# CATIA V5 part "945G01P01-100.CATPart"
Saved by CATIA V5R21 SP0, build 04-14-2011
Part number: 945G01P01-100
Bounding box of the stored display mesh (mm): x -11.215 to 11.225, y -4.875 to 4.875, z -50.1 to 50.1
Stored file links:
  C:\Users\ALI OZGUN\Desktop\alhan\945G01P01-100.CATPart
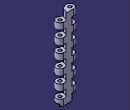
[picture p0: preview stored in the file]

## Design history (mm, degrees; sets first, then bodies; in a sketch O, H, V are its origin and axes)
Body1 (main body)
  Sketch1 on xy-plane, origin (0, 0, 0), H (1, 0, 0), V (0, 1, 0)
    construction line L1 (-6.35, 0) -> (6.35, 0)
    point P1 (-6.35, 0)
    point P2 (6.35, 0)
    line L2 (-6.35, 4.875) -> (6.35, 4.875)
    line L3 (6.35, -4.875) -> (-6.35, -4.875)
    arc A1 centre (6.35, 0) radius 4.875 from (6.35, 4.875) to (6.35, -4.875) cw
    arc A2 centre (-6.35, 0) radius 4.875 from (-6.35, -4.875) to (-6.35, 4.875) cw
    distance L1 L2 = 4.875
    length L1 = 12.7
    distance P2 V = 6.35
    coincidence: P1 H
    horizontal: L1 H
    tangency: A1 L2, A2 L2, A1 L3, A2 L3
  Pad1: profile Sketch1, direction (0, 0, 1), length 50.1, mirrored extent
  Body2
    Sketch2 on zx-plane, origin (0, 0, 0), H (-1, 0, 0), V (0, 0, 1)
      line L1 (-17.4249, -33.3) -> (-3.75, -33.3)
      line L2 (-3.75, -33.3) -> (-3.75, -42.1)
      line L3 (-3.75, -42.1) -> (-17.4249, -42.1)
      line L4 (-17.4249, -42.1) -> (-17.4249, -33.3)
      line L5 (3.75, -41.7) -> (15.9148, -41.7)
      line L6 (15.9148, -41.7) -> (15.9148, -50.5)
      line L7 (15.9148, -50.5) -> (3.75, -50.5)
      line L8 (3.75, -50.5) -> (3.75, -41.7)
      reference projected line E1 (-6.35, -50.1) -> (6.35, -50.1) from edge [start face of Pad1 | face of Pad1 from Sketch1.L2]
      reference projected line E2 (-6.35, -50.1) -> (6.35, -50.1) from edge [start face of Pad1 | face of Pad1 from Sketch1.L2]
      distance L3 E1 = 8
      length L4 = 8.8
      distance L2 L8 = 7.5
      distance L8 V = 3.75
      distance L5 L7 = 8.8
      distance L5 E2 = 8.4
      horizontal: L1 H, L3 H, L5 H, L7 H
      vertical: L2 V, L4 V, L6 V, L8 V
    Pad2: profile Sketch2, direction (0, 1, 0), length 20, mirrored extent
    RectPattern1: of the body so far, direction 1 instances 6, spacing 16.8, along axis of face of Pad1 from Sketch1.A2
  Remove1: tool Body2
  Sketch3 on xy-plane, origin (0, 0, 0), H (1, 0, 0), V (0, 1, 0)
    line L1 (-2.8809, -3.425) -> (2.8809, -3.425)
    reference projected line E1 (6.35, 4.875) -> (-6.35, 4.875) from edge [face of Pad1 from Sketch1.L2 | end face of Pad1]
    projected arc E2 centre (6.35, 0) radius 4.875 from (6.35, -4.875) to (6.35, 4.875) ccw from edge [face of Pad1 from Sketch1.A1 | face of RectPattern1]
    projected arc E3 centre (6.35, 0) radius 4.875 from (2.8809, -3.425) to (6.35, -4.875) ccw from edge [face of Pad1 from Sketch1.A1 | face of RectPattern1]
    projected arc E4 centre (-6.35, 0) radius 4.875 from (-6.35, 4.875) to (-6.35, -4.875) ccw from edge [face of Pad1 from Sketch1.A2 | end face of Pad1]
    projected arc E5 centre (-6.35, 0) radius 4.875 from (-6.35, -4.875) to (-2.8809, -3.425) ccw from edge [face of Pad1 from Sketch1.A2 | end face of Pad1]
    circle A1 centre (6.35, 0) radius 2
    point P7 (6.35, 0)
    circle A2 centre (-6.35, 0) radius 2
    point P8 (-6.35, 0)
    projected line E6 (-6.35, -4.875) -> (3.75, -4.875) from edge [face of Pad1 from Sketch1.L3 | end face of Pad1]
    projected line E7 (-6.35, -4.875) -> (6.35, -4.875) from edge [face of Pad1 from Sketch1.L3 | end face of Pad1]
    distance E1 L1 = 8.3
    radius A1 = 2
    radius A2 = 2
    horizontal: L1 H
    concentricity: P7 E2, P8 E4
  Pocket1: profile Sketch3, direction (0, 0, -1), length 50.1, mirrored extent
  Body3
    Solid1: linked copy from another document
    Translate1: Direction yz-plane, ToTransfor Solid1, Length 25.4
  Remove2: tool Body3
  Body4
    Solid2: solid without history
    Translate2: Direction yz-plane, ToTransfor Solid2, Length -12.7
    Thickness1: Face face of Solid2, Thickness 0.5
    Thickness2: Face (face of Solid2; face of Solid2; face of Solid2; face of Solid2; face of Solid2; face of Solid2; face of Solid2; face of Solid2; face of Solid2; face of Solid2; face of Solid2; face of Solid2), Thickness -2.5
    Thickness3: Face (face of Solid2; face of Solid2; face of Solid2; face of Solid2; face of Solid2; face of Solid2; face of Solid2; face of Solid2; face of Solid2; face of Solid2; face of Solid2; face of Solid2; face of Solid2; face of Solid2; face of Solid2; face of Solid2; face of Solid2; face of Solid2; face of Solid2; face of Solid2; face of Solid2; face of Solid2; face of Solid2; face of Solid2), Thickness 0.4
  Remove3: tool Body4
  Chamfer1: length 3, angle 45, on edge [face of Solid2 | face of Pocket1 from Sketch3.L1]; edge [face of Solid1 | face of Pocket1 from Sketch3.L1] (x6); edge [face of Pocket1 from Sketch3.L1 | face of Solid2] (x5)
  Sketch4 on start face of Pad1, origin (0, 0, -50.1), H (1, 0, 0), V (0, -1, 0)
    point P1 (6.35, -3.275)
    point P2 (-3.75, -3.275)
    arc A1 centre (6.35, 0) radius 3.25 from (3.1063, -0.2016) to (8.9441, -1.9578) ccw
    reference projected arc E1 centre (6.35, 0) radius 4.875 from (6.35, -4.875) to (6.35, 4.875) ccw from edge [start face of Pad1 | face of Pocket1]
    line L1 (3.1063, -0.2016) -> (2.8809, 3.425)
    reference projected point E2 (2.8809, 3.425) from edge [face of Pocket1 from Sketch3.L1 | face of Pocket1]
    projected arc E3 centre (6.35, 0) radius 4.875 from (6.35, -4.875) to (2.8809, 3.425) ccw from edge [start face of Pad1 | face of Pocket1]
    projected arc E4 centre (6.35, 0) radius 4.875 from (10.2924, -2.8676) to (2.8809, 3.425) ccw from edge [start face of Pad1 | face of Pocket1]
    line L2 (8.9441, -1.9578) -> (10.2924, -2.8676)
    distance P1 P2 = 10.1
    radius A1 = 3.25
    concentricity: A1 E1
    coincidence: L1 E2
    tangency: L1 A1
  Pocket2: profile Sketch4, direction (0, 0, 1), length 2.8
  Fillet1: radius 0.5, on edge [face of Pocket2 from Sketch4.L2 | face of Pocket2 from Sketch4.A1]; edge [face of Pocket1 | face of Pocket2 from Sketch4.L2]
